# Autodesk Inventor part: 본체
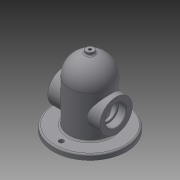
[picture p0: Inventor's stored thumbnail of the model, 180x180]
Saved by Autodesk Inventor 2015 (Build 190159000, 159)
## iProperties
Created: 2019-11
Part Number: 본체
Material: 일반
Document SubType Name: Modeling
Designer: now
Density: 1 g/cm^3
Appearance: 기본값
Author: now
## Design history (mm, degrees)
sketch "스케치1"
  geometry: C1 r 70 at (0, 0); 1 further point
  constraints: 1 centre point, 1 coincident
  dimensions: "d0" = 140 diameter of C1
extrude "돌출1" new body sketch "스케치1" distance "d1" = 10; taper "d2" = 0 deg
sketch "스케치2"
  geometry: C1 r 70 at (0, 0) reference; C2 r 40 at (0, 0)
  constraints: 1 centre point, 1 coincident
  dimensions: "d3" = 80 diameter of C2
extrude "돌출2" join sketch "스케치2" distance "d4" = 120; taper "d5" = 0 deg
fillet "모깎기1" dims "d6" = 40
node "작업 평면1"
feature "쉘1" dims "d12" = 10
node "작업 평면2"
sketch "스케치4"
  geometry: L1 (-70, 0)-(70, 0) reference; C1 r 31 at (0, 50); 2 further points
  constraints: 1 centre point, 1 coincident, 1 vertical alignment
  dimensions: "d14" = 50 distance from line of L1 point (0, 50); "d15" = 62 diameter of C1
extrude "돌출4" join sketch "스케치4" distance "d16" = 100; taper "d17" = 0 deg
node "작업 평면3"
sketch "스케치5"
  geometry: C1 r 7.5 at (0, 0); 1 further point
  constraints: 1 centre point, 1 coincident
  dimensions: "d19" = 15 diameter of C1
extrude "돌출5" join sketch "스케치5" stored distance "d20" = 15 (= d19); taper "d21" = 0 deg
sketch "스케치6"
  geometry: C1 r 31 at (0, 0) reference; C2 r 16.5 at (0, 0); 1 further point
  constraints: 1 centre point, 1 coincident
  dimensions: "d22" = 33 diameter of C2
extrude "돌출6" cut sketch "스케치6" stored distance "d23" = 100; taper "d24" = 0 deg
sketch "스케치7"
  geometry: C1 r 16.5 at (0, 0) reference; C2 r 31 at (0, 0) reference; C3 r 20 at (0, 0); 1 further point
  constraints: 1 centre point, 1 coincident
  dimensions: "d25" = 40 diameter of C3
extrude "돌출7" cut sketch "스케치7" distance "d26" = 15; taper "d27" = 0 deg
sketch "스케치8"
  geometry: C1 r 16.5 at (0, 0) reference; C2 r 31 at (0, 0) reference; C3 r 20 at (0, 0); 1 further point
  constraints: 1 centre point, 1 coincident
  dimensions: "d28" = 40 diameter of C3
extrude "돌출8" cut sketch "스케치8" distance "d29" = 15; taper "d30" = 0 deg
sketch "스케치9"
  geometry: C1 r 7.5 at (0, 0) reference
hole "구멍1" sketch "스케치9" at (0, 0) diameter "d31" = 5.188; stored, may be unused: countersink angle "d35" = 90 deg, drill point angle "d37" = 118 deg; dims "d32" = 12, "d33" = 4, "d34" = 2, "d36" = 30
sketch "스케치10"
  geometry: C1 r 30 at (0, 0) reference; C2 r 70 at (0, 0) reference; C3 r 30 at (0, 0)
  constraints: 1 centre point, 1 coincident
  dimensions: "d38" = 60 diameter of C3
extrude "돌출9" cut sketch "스케치10" stored distance "d39" = 15; taper "d40" = 0 deg
sketch "스케치11"
  geometry: C1 r 20 at (0, 0) reference; 2 further points
  constraints: 1 horizontal alignment
  dimensions: "d41" = 26 distance of C1.centre point (-26, 0)
hole "구멍2" sketch "스케치11" at (-26, 0) diameter "d42" = 3.242; stored, may be unused: countersink angle "d46" = 90 deg, drill point angle "d48" = 118 deg; dims "d43" = 8, "d44" = 4, "d45" = 2, "d47" = 10
node "작업 평면4"
sketch "스케치12"
  geometry: L1 (-70, 0)-(70, 0) reference; 2 further points
  constraints: 1 vertical alignment, 1 other
  dimensions: "d53" = 50 distance from line of L1 point (0, 50)
feature "엠보싱1" sketch "스케치12" dims "d54" = 0.5, "d55" = 0
sketch "스케치13" dims "d56" = 110
  geometry: C1 r 70 at (0, 0) reference; C2 r 4.5 at (0, -55); 1 further point
  constraints: 1 centre point, 1 coincident, 1 vertical alignment, 2 other
  dimensions: "d57" = 9 diameter of C2
extrude "돌출10" cut sketch "스케치13" stored distance "d58" = 15; taper "d59" = 0 deg
fillet "모깎기2" dims "d60" = 3
chamfer "모따기1" distance "d61" = 1; stored, may be unused: second distance "d62" = 2, angle "d63" = 45 deg
fillet "모깎기3" dims "d64" = 0.3
node "솔리드1"
pattern_circular "원형 패턴1" dims angle "d50" = 360 deg
mirror "대칭1"
mirror "대칭2"
other parameters: "d18" = 135
